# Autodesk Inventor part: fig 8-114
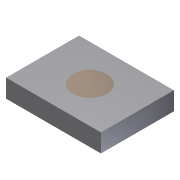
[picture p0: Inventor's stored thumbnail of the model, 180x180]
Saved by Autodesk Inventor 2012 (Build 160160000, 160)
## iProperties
Created: 2009-09
Part Number: fig 8-114
Document SubType Name: Modeling
Designer: Sham
Density: 1 g/cm^3
Material: Default
Author: Sham
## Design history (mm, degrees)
sketch "Sketch1"
  geometry: L1 (-26, 20)-(0, 20); L2 (0, 20)-(0, 0); L3 (0, 0)-(-26, 0); L4 (-26, 0)-(-26, 20)
  constraints: 8 end point, 2 parallel, 1 horizontal, 1 perpendicular
extrude "Extrusion1" new body sketch "Sketch1" distance "d0" = 5; taper "d1" = 0 deg
workplane "Work Plane1"
sketch "Sketch2"
  geometry: L1 (13, 8)-(13, 5); A1 r 7.517 centre (12.377, -0.349) between (17.658, 5) and (13, 7.142)
  constraints: 2 end point, 2 point on circle, 1 centre point
feature "RevolutionSrf2" sketch "Sketch2" dims angle "d4" = 90 deg
body "Solid1"
body "Srf2"
